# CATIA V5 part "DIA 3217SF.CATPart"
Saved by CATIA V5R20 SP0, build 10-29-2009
Part number: DIA 3217SF
Revision: ANY
Definition: UNKNOWN
Nomenclature: DIA 3217SF
Source: Unknown
Bounding box of the stored display mesh (mm): x -1.6 to 1.6, y -8.75 to 8.2, z -1.6 to 1.6
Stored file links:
  C:\Users\Utente\Desktop\IO LAVORO\3D X SITO CF\CUMSA\3D files FA\FA 063205-21\DIA 3217SF.CATPart

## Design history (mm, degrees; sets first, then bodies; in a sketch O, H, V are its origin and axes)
Body1 "Cortar-Extruir2" (main body)
  Solid1: solid without history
